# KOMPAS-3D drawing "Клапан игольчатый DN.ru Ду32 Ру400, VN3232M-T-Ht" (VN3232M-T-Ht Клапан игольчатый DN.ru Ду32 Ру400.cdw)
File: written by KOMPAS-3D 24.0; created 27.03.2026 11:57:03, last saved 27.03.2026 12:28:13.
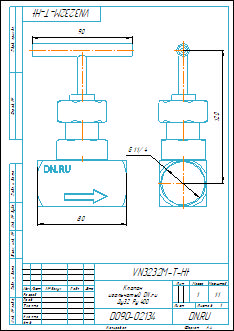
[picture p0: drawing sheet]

Document properties: Автор: Илья; Форматы листов документа: A4; Полное имя файла: VN3232M-T-Ht Клапан игольчатый DN.ru Ду32 Ру400.m3d; Масса: 1; Наименование: Клапан игольчатый DN.ru Ду32 Ру400; Количество листов документа: 1; Примечание: D090-02134

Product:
- Body: Body10  | qty 1
    Масса: 1.287778
- Part/product: Клапан игольчатый DN.ru Ду32 Ру400  | designation VN3232M-T-Ht
    Масса: 1
    Раздел спецификации: Прочие изделия
    Примечание: D090-02134

Views: Вид 1, Слева
Referenced files in D:\Обмен\Заказы с фриланса\DN.ru\VNxxM-T-Ht Клапан игольчатый DN.ru Ду8-50 Ру400\VN3232M-T-Ht Клапан игольчатый DN.ru Ду8-50 Ру400\DN8\: VN3232M-T-Ht Клапан игольчатый DN.ru Ду8 Ру400.m3d, VN3232M-T-Ht Клапан игольчатый DN.ru Ду8 Ру400.cdw
Referenced files in D:\Обмен\Заказы с фриланса\DN.ru\VNxxM-T-Ht Клапан игольчатый DN.ru Ду8-50 Ру400\VN3232M-T-Ht Клапан игольчатый DN.ru Ду8-50 Ру400\DN32\: VN3232M-T-Ht Клапан игольчатый DN.ru Ду32 Ру400.m3d
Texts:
  VN3232M-T-Ht
  Клапан
  игольчатый DN.ru
  Ду32 Ру400
  Body10
  Клапан игольчатый DN.ru Ду32 Ру400
  VN3232M-T-Ht Клапан игольчатый DN.ru Ду32 Ру400
Dimensions and other numbers on the sheet: 0; 3; 2; 4; 80; 90; 1:1; 1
